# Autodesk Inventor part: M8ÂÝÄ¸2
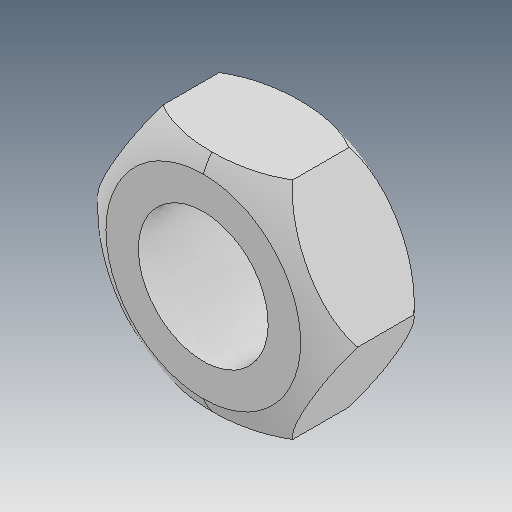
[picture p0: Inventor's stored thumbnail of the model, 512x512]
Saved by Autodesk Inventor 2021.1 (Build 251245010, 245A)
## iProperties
Created: 2019-04
Part Number: M8ÂÝÄ¸2
Material: Ogólny
Document SubType Name: Modeling
Designer: user
Density: 1 g/cm^3
Appearance: Domyślna
Author: user
Revision Number: ÈÎºÎ
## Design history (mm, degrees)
feature "ÊäÈë1"
node "Bryła1"
